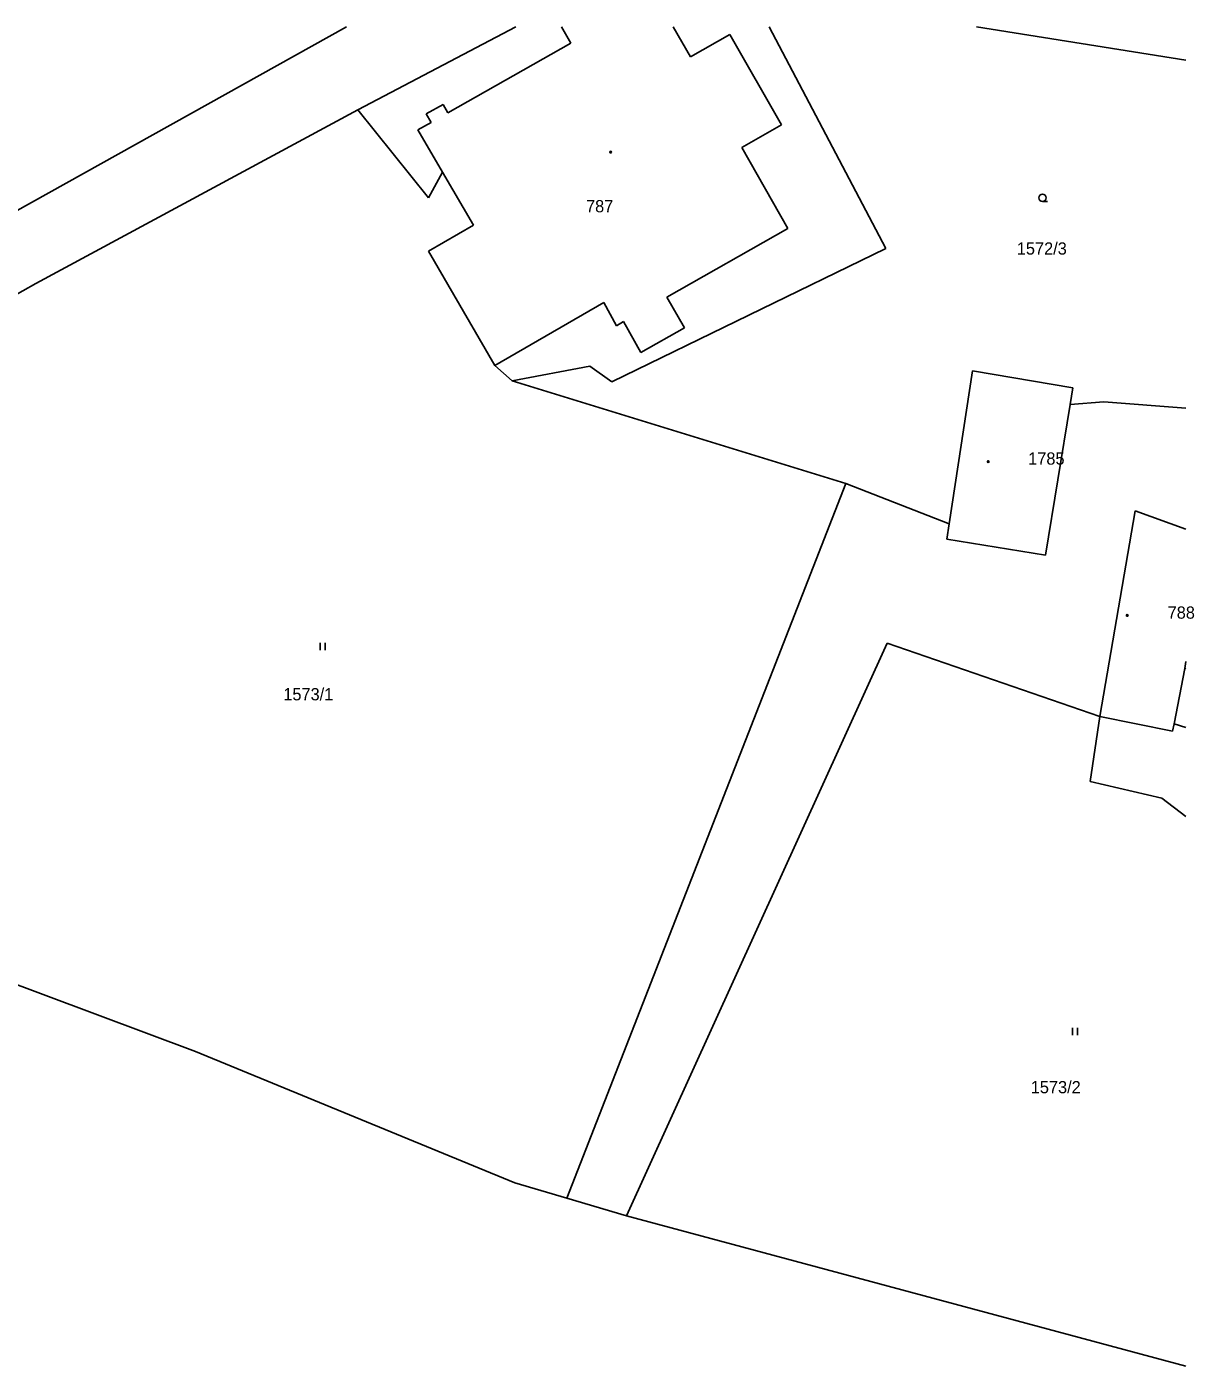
# Model space of a CAD drawing. Extents: x -866624 to -866276, y -1050208 to -1049940.
# Drawn here: x -866323.5 to -866275.7, y -1049995 to -1049940.2 of the extents above; entities that cross this region are included whole.
import ezdxf

# ---------------------------------------------------------------- set-up
doc = ezdxf.new("R2010")
doc.units = 0
for name, color, linetype in [('Default', 7, 'Continuous'), ('Hranice', 7, 'Continuous'), ('Hranice další', 7, 'Continuous'), ('Hranice-budov', 7, 'Continuous'), ('Parcela-pozemkova', 7, 'Continuous'), ('Parcela-stavebni', 7, 'Continuous'), ('znacky-budov', 7, 'Continuous'), ('Znacky-kultury', 7, 'Continuous')]:
    doc.layers.add(name, color=color, linetype=linetype)

# ---------------------------------------------------------------- blocks, each defined once
blk = doc.blocks.new('p_zahr')
at = {"layer": 'Default'}
blk.add_line((0, -0.75), (0.99, -0.75), dxfattribs=at)
blk.add_circle((0, 0), 0.75, dxfattribs=at)
blk = doc.blocks.new('p_louka')
at = {"layer": 'Default'}
for p, q in [((-0.47, 0.72), (-0.47, -0.78)), ((0.53, 0.72), (0.53, -0.78))]:
    blk.add_line(p, q, dxfattribs=at)
blk = doc.blocks.new('s_zdena')
at = {"layer": 'Default'}
blk.add_circle((0, 0), 0.175, dxfattribs=at)
for start, end in [(0, 180), (180, 0)]:
    blk.add_arc((0, 0), 0.0875, start, end, dxfattribs=at)

msp = doc.modelspace()

# ---------------------------------------------------------------- linework, layer by layer
at = {"layer": 'Hranice'}
for p, q in [((-866329.42, -1049950.83), (-866310.404, -1049940.226)), ((-866303.479, -1049940.226), (-866309.94, -1049943.62)), ((-866293.115, -1049940.226), (-866288.35, -1049949.3)), ((-866276.08, -1049941.591), (-866284.638, -1049940.226)), ((-866323.1, -1049950.72), (-866309.94, -1049943.62)), ((-866307.05, -1049947.22), (-866309.94, -1049943.62)), ((-866307.05, -1049947.22), (-866306.47, -1049946.17)), ((-866306.47, -1049946.17), (-866305.21, -1049948.34)), ((-866307.04, -1049949.4), (-866305.21, -1049948.34)), ((-866288.35, -1049949.3), (-866299.55, -1049954.75)), ((-866307.04, -1049949.4), (-866304.33, -1049954.08)), ((-866323.1, -1049950.72), (-866330.63, -1049954.99)), ((-866304.33, -1049954.08), (-866303.62, -1049954.71)), ((-866300.45, -1049954.11), (-866303.62, -1049954.71)), ((-866299.55, -1049954.75), (-866300.45, -1049954.11)), ((-866303.62, -1049954.71), (-866289.98, -1049958.9)), ((-866284.8, -1049954.3), (-866285.76, -1049960.55)), ((-866284.8, -1049954.3), (-866280.7, -1049954.99)), ((-866280.7, -1049954.99), (-866280.81, -1049955.67)), ((-866281.82, -1049961.84), (-866280.81, -1049955.67)), ((-866280.81, -1049955.67), (-866279.43, -1049955.57)), ((-866276.08, -1049955.823), (-866279.43, -1049955.57)), ((-866301.39, -1049988.13), (-866289.98, -1049958.9)), ((-866285.76, -1049960.55), (-866289.98, -1049958.9)), ((-866285.76, -1049960.55), (-866285.86, -1049961.18)), ((-866285.86, -1049961.18), (-866281.82, -1049961.84)), ((-866288.3, -1049965.43), (-866298.95, -1049988.86)), ((-866288.3, -1049965.43), (-866279.6, -1049968.43)), ((-866276.08, -1049966.183), (-866276.13, -1049966.47)), ((-866276.13, -1049966.47), (-866276.56, -1049968.73)), ((-866279.6, -1049968.43), (-866280, -1049971.09)), ((-866279.6, -1049968.43), (-866276.63, -1049969.03)), ((-866276.56, -1049968.73), (-866276.63, -1049969.03)), ((-866280, -1049971.09), (-866277.07, -1049971.78)), ((-866277.07, -1049971.78), (-866276.08, -1049972.518)), ((-866328.67, -1049977.61), (-866316.57, -1049982.13)), ((-866303.51, -1049987.5), (-866316.57, -1049982.13)), ((-866303.51, -1049987.5), (-866301.39, -1049988.13)), ((-866301.39, -1049988.13), (-866298.95, -1049988.86)), ((-866276.08, -1049995.006), (-866298.95, -1049988.86))]:
    msp.add_line(p, q, dxfattribs=at)
at = {"layer": 'Hranice další'}
for p, q in [((-866301.23, -1049940.89), (-866301.609, -1049940.226)), ((-866296.34, -1049941.46), (-866297.038, -1049940.226)), ((-866296.34, -1049941.46), (-866294.72, -1049940.54)), ((-866294.72, -1049940.54), (-866292.62, -1049944.24)), ((-866306.25, -1049943.74), (-866301.23, -1049940.89)), ((-866306.45, -1049943.4), (-866307.14, -1049943.79)), ((-866307.14, -1049943.79), (-866306.94, -1049944.14)), ((-866306.25, -1049943.74), (-866306.45, -1049943.4)), ((-866306.94, -1049944.14), (-866307.48, -1049944.44)), ((-866292.62, -1049944.24), (-866294.24, -1049945.16)), ((-866306.47, -1049946.17), (-866307.48, -1049944.44)), ((-866294.24, -1049945.16), (-866292.36, -1049948.47)), ((-866292.36, -1049948.47), (-866297.3, -1049951.28)), ((-866304.33, -1049954.08), (-866299.88, -1049951.5)), ((-866299.36, -1049952.45), (-866299.88, -1049951.5)), ((-866296.58, -1049952.54), (-866297.3, -1049951.28)), ((-866299.08, -1049952.28), (-866299.36, -1049952.45)), ((-866299.08, -1049952.28), (-866298.36, -1049953.55)), ((-866296.58, -1049952.54), (-866298.36, -1049953.55)), ((-866279.6, -1049968.43), (-866278.16, -1049960.02)), ((-866276.08, -1049960.769), (-866278.16, -1049960.02)), ((-866276.13, -1049966.47), (-866276.08, -1049966.48)), ((-866276.08, -1049968.881), (-866276.56, -1049968.73))]:
    msp.add_line(p, q, dxfattribs=at)
at = {"layer": 'Hranice-budov'}
for p, q in [((-866301.23, -1049940.89), (-866301.609, -1049940.226)), ((-866296.34, -1049941.46), (-866297.038, -1049940.226)), ((-866296.34, -1049941.46), (-866294.72, -1049940.54)), ((-866294.72, -1049940.54), (-866292.62, -1049944.24)), ((-866306.25, -1049943.74), (-866301.23, -1049940.89)), ((-866306.45, -1049943.4), (-866307.14, -1049943.79)), ((-866307.14, -1049943.79), (-866306.94, -1049944.14)), ((-866306.25, -1049943.74), (-866306.45, -1049943.4)), ((-866306.94, -1049944.14), (-866307.48, -1049944.44)), ((-866292.62, -1049944.24), (-866294.24, -1049945.16)), ((-866306.47, -1049946.17), (-866307.48, -1049944.44)), ((-866294.24, -1049945.16), (-866292.36, -1049948.47)), ((-866306.47, -1049946.17), (-866305.21, -1049948.34)), ((-866307.04, -1049949.4), (-866305.21, -1049948.34)), ((-866292.36, -1049948.47), (-866297.3, -1049951.28)), ((-866307.04, -1049949.4), (-866304.33, -1049954.08)), ((-866304.33, -1049954.08), (-866299.88, -1049951.5)), ((-866299.36, -1049952.45), (-866299.88, -1049951.5)), ((-866296.58, -1049952.54), (-866297.3, -1049951.28)), ((-866299.08, -1049952.28), (-866299.36, -1049952.45)), ((-866299.08, -1049952.28), (-866298.36, -1049953.55)), ((-866296.58, -1049952.54), (-866298.36, -1049953.55)), ((-866284.8, -1049954.3), (-866285.76, -1049960.55)), ((-866284.8, -1049954.3), (-866280.7, -1049954.99)), ((-866280.7, -1049954.99), (-866280.81, -1049955.67)), ((-866281.82, -1049961.84), (-866280.81, -1049955.67)), ((-866279.6, -1049968.43), (-866278.16, -1049960.02)), ((-866276.08, -1049960.769), (-866278.16, -1049960.02)), ((-866285.76, -1049960.55), (-866285.86, -1049961.18)), ((-866285.86, -1049961.18), (-866281.82, -1049961.84)), ((-866276.08, -1049966.183), (-866276.13, -1049966.47)), ((-866276.13, -1049966.47), (-866276.56, -1049968.73)), ((-866279.6, -1049968.43), (-866276.63, -1049969.03)), ((-866276.56, -1049968.73), (-866276.63, -1049969.03))]:
    msp.add_line(p, q, dxfattribs=at)

# ---------------------------------------------------------------- block references
at = {"layer": 'znacky-budov', "xscale": 0.2, "yscale": 0.20000000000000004}
for p in [(-866299.6, -1049945.35), (-866284.16, -1049958.01), (-866278.48, -1049964.3)]:
    msp.add_blockref('s_zdena', p, dxfattribs=at)
at = {"layer": 'Znacky-kultury', "xscale": 0.2, "yscale": 0.20000000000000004}
for name, p in [('p_zahr', (-866281.94, -1049947.22)), ('p_louka', (-866311.38, -1049965.57)), ('p_louka', (-866280.62, -1049981.31))]:
    msp.add_blockref(name, p, dxfattribs=at)

# ---------------------------------------------------------------- texts
at = {"layer": 'Parcela-pozemkova'}
for s, p in [('1572/3', (-866282.994, -1049949.543)), ('1573/1', (-866312.983, -1049967.773)), ('1573/2', (-866282.424, -1049983.843))]:
    msp.add_text(s, height=0.5, dxfattribs=at).set_placement(p)
at = {"layer": 'Parcela-stavebni'}
for s, p in [('787', (-866300.607, -1049947.813)), ('1785', (-866282.529, -1049958.133)), ('788', (-866276.827, -1049964.433))]:
    msp.add_text(s, height=0.5, dxfattribs=at).set_placement(p)

doc.saveas('drawing.dxf')
